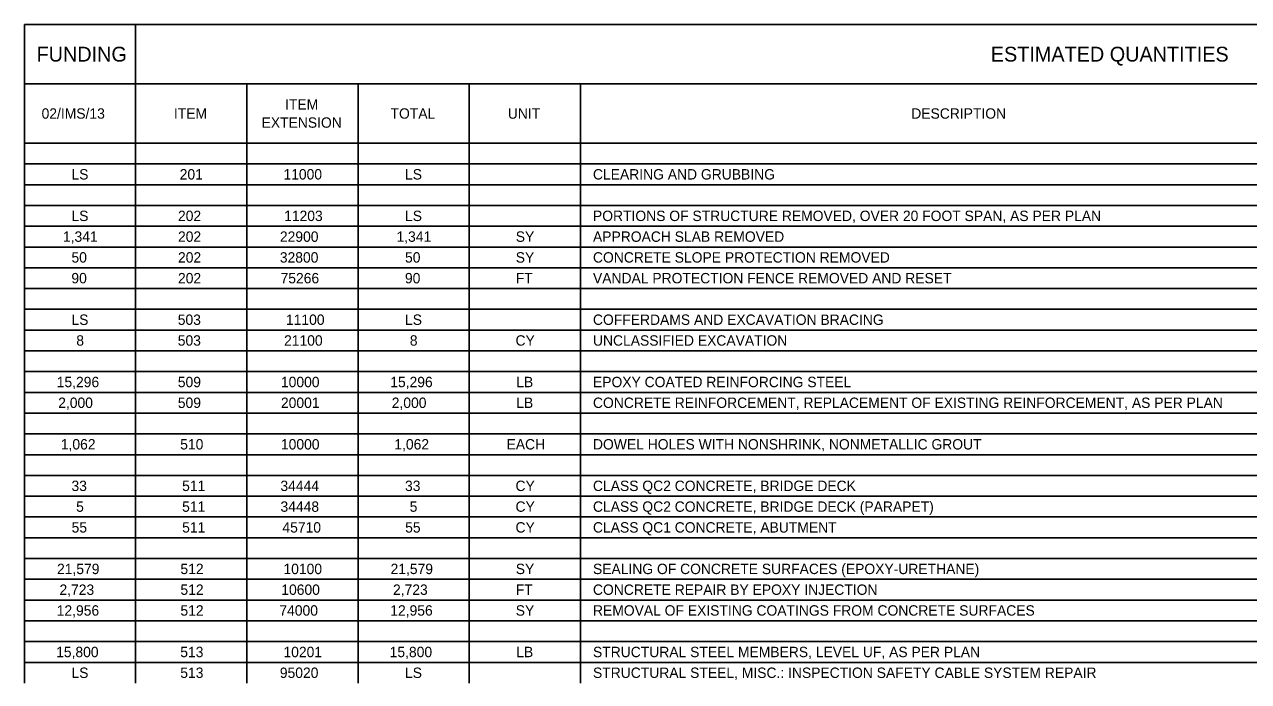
# Model space of a CAD drawing. Extents: x 100 to 128, y 64.8 to 100.
# Drawn here: x 100 to 116.51, y 91.14 to 100 of the extents above; entities that cross this region are included whole.
import ezdxf

# ---------------------------------------------------------------- set-up
doc = ezdxf.new("R2010")
doc.units = 0
doc.layers.add('SH_Text', color=7, linetype='Continuous')

msp = doc.modelspace()

# ---------------------------------------------------------------- linework, layer by layer
at = {"layer": 'SH_Text'}
for p, q in [((100, 100), (128, 100)), ((100, 100), (100, 98.4)), ((101.5, 100), (101.5, 98.4)), ((100, 99.2), (128, 99.2)), ((103, 99.2), (103, 98.4)), ((104.5, 99.2), (104.5, 98.4)), ((106, 99.2), (106, 98.4)), ((107.5, 99.2), (107.5, 98.4)), ((100, 98.4), (128, 98.4)), ((100, 98.4), (128, 98.4)), ((100, 98.4), (100, 95.32)), ((101.5, 98.4), (101.5, 95.32)), ((103, 98.4), (103, 95.32)), ((104.5, 98.4), (104.5, 95.32)), ((106, 98.4), (106, 95.32)), ((107.5, 98.4), (107.5, 95.32)), ((100, 98.12), (128, 98.12)), ((100, 97.84), (128, 97.84)), ((100, 97.56), (128, 97.56)), ((100, 97.28), (128, 97.28)), ((100, 97), (128, 97)), ((100, 96.72), (128, 96.72)), ((100, 96.44), (128, 96.44)), ((100, 96.16), (128, 96.16)), ((100, 95.88), (128, 95.88)), ((100, 95.6), (128, 95.6)), ((100, 95.32), (128, 95.32)), ((100, 95.32), (100, 92.24)), ((101.5, 95.32), (101.5, 92.24)), ((103, 95.32), (103, 92.24)), ((104.5, 95.32), (104.5, 92.24)), ((106, 95.32), (106, 92.24)), ((107.5, 95.32), (107.5, 92.24)), ((100, 95.04), (128, 95.04)), ((100, 94.76), (128, 94.76)), ((100, 94.48), (128, 94.48)), ((100, 94.2), (128, 94.2)), ((100, 93.92), (128, 93.92)), ((100, 93.64), (128, 93.64)), ((100, 93.36), (128, 93.36)), ((100, 93.08), (128, 93.08)), ((100, 92.8), (128, 92.8)), ((100, 92.52), (128, 92.52)), ((100, 92.24), (128, 92.24)), ((100, 92.24), (100, 91.96)), ((101.5, 92.24), (101.5, 91.96)), ((103, 92.24), (103, 91.96)), ((104.5, 92.24), (104.5, 91.96)), ((106, 92.24), (106, 91.96)), ((107.5, 92.24), (107.5, 91.96)), ((100, 91.96), (128, 91.96)), ((100, 91.96), (100, 91.68)), ((101.5, 91.96), (101.5, 91.68)), ((103, 91.96), (103, 91.68)), ((104.5, 91.96), (104.5, 91.68)), ((106, 91.96), (106, 91.68)), ((107.5, 91.96), (107.5, 91.68)), ((100, 91.68), (128, 91.68)), ((100, 91.68), (100, 91.4)), ((101.5, 91.68), (101.5, 91.4)), ((103, 91.68), (103, 91.4)), ((104.5, 91.68), (104.5, 91.4)), ((106, 91.68), (106, 91.4)), ((107.5, 91.68), (107.5, 91.4)), ((100, 91.4), (128, 91.4)), ((100, 91.4), (100, 91.12)), ((101.5, 91.4), (101.5, 91.12)), ((103, 91.4), (103, 91.12)), ((104.5, 91.4), (104.5, 91.12)), ((106, 91.4), (106, 91.12)), ((107.5, 91.4), (107.5, 91.12))]:
    msp.add_line(p, q, dxfattribs=at)

# ---------------------------------------------------------------- texts
for s, height, p in [('FUNDING', 0.2, (100.163, 99.5)), ('ESTIMATED QUANTITIES', 0.2, (113.037, 99.5)), ('ITEM', 0.14, (103.516, 98.852)), ('02/IMS/13', 0.14, (100.231, 98.73)), ('ITEM', 0.14, (102.016, 98.73)), ('TOTAL', 0.14, (104.939, 98.73)), ('UNIT', 0.14, (106.521, 98.73)), ('DESCRIPTION', 0.14, (111.964, 98.73)), ('EXTENSION', 0.14, (103.199, 98.608)), ('LS', 0.14, (100.634, 97.91)), ('201', 0.14, (102.094, 97.91)), ('11000', 0.14, (103.494, 97.91)), ('LS', 0.14, (105.134, 97.91)), ('CLEARING AND GRUBBING', 0.14, (107.67, 97.91)), ('LS', 0.14, (100.634, 97.35)), ('202', 0.14, (102.071, 97.35)), ('11203', 0.14, (103.503, 97.35)), ('LS', 0.14, (105.134, 97.35)), ('PORTIONS OF STRUCTURE REMOVED, OVER 20 FOOT SPAN, AS PER PLAN', 0.14, (107.67, 97.35)), ('1,341', 0.14, (100.519, 97.07)), ('202', 0.14, (102.071, 97.07)), ('22900', 0.14, (103.446, 97.07)), ('1,341', 0.14, (105.019, 97.07)), ('SY', 0.14, (106.628, 97.07)), ('APPROACH SLAB REMOVED', 0.14, (107.67, 97.07)), ('50', 0.14, (100.634, 96.79)), ('202', 0.14, (102.071, 96.79)), ('32800', 0.14, (103.445, 96.79)), ('50', 0.14, (105.134, 96.79)), ('SY', 0.14, (106.628, 96.79)), ('CONCRETE SLOPE PROTECTION REMOVED', 0.14, (107.67, 96.79)), ('90', 0.14, (100.633, 96.51)), ('202', 0.14, (102.071, 96.51)), ('75266', 0.14, (103.455, 96.51)), ('90', 0.14, (105.133, 96.51)), ('FT', 0.14, (106.628, 96.51)), ('VANDAL PROTECTION FENCE REMOVED AND RESET', 0.14, (107.67, 96.51)), ('LS', 0.14, (100.634, 95.95)), ('503', 0.14, (102.068, 95.95)), ('11100', 0.14, (103.528, 95.95)), ('LS', 0.14, (105.134, 95.95)), ('COFFERDAMS AND EXCAVATION BRACING', 0.14, (107.67, 95.95)), ('8', 0.14, (100.699, 95.67)), ('503', 0.14, (102.068, 95.67)), ('21100', 0.14, (103.502, 95.67)), ('8', 0.14, (105.199, 95.67)), ('CY', 0.14, (106.625, 95.67)), ('UNCLASSIFIED EXCAVATION', 0.14, (107.67, 95.67)), ('15,296', 0.14, (100.435, 95.11)), ('509', 0.14, (102.069, 95.11)), ('10000', 0.14, (103.46, 95.11)), ('15,296', 0.14, (104.935, 95.11)), ('LB', 0.14, (106.635, 95.11)), ('EPOXY COATED REINFORCING STEEL', 0.14, (107.67, 95.11)), ('2,000', 0.14, (100.455, 94.83)), ('509', 0.14, (102.069, 94.83)), ('20001', 0.14, (103.46, 94.83)), ('2,000', 0.14, (104.955, 94.83)), ('LB', 0.14, (106.635, 94.83)), ('CONCRETE REINFORCEMENT, REPLACEMENT OF EXISTING REINFORCEMENT, AS PER PLAN', 0.14, (107.67, 94.83)), ('1,062', 0.14, (100.49, 94.27)), ('510', 0.14, (102.101, 94.27)), ('10000', 0.14, (103.46, 94.27)), ('1,062', 0.14, (104.99, 94.27)), ('EACH', 0.14, (106.504, 94.27)), ('DOWEL HOLES WITH NONSHRINK, NONMETALLIC GROUT', 0.14, (107.67, 94.27)), ('33', 0.14, (100.634, 93.71)), ('511', 0.14, (102.127, 93.71)), ('34444', 0.14, (103.453, 93.71)), ('33', 0.14, (105.134, 93.71)), ('CY', 0.14, (106.625, 93.71)), ('CLASS QC2 CONCRETE, BRIDGE DECK', 0.14, (107.67, 93.71)), ('5', 0.14, (100.697, 93.43)), ('511', 0.14, (102.127, 93.43)), ('34448', 0.14, (103.454, 93.43)), ('5', 0.14, (105.197, 93.43)), ('CY', 0.14, (106.625, 93.43)), ('CLASS QC2 CONCRETE, BRIDGE DECK (PARAPET)', 0.14, (107.67, 93.43)), ('55', 0.14, (100.636, 93.15)), ('511', 0.14, (102.127, 93.15)), ('45710', 0.14, (103.48, 93.15)), ('55', 0.14, (105.136, 93.15)), ('CY', 0.14, (106.625, 93.15)), ('CLASS QC1 CONCRETE, ABUTMENT', 0.14, (107.67, 93.15)), ('21,579', 0.14, (100.439, 92.59)), ('512', 0.14, (102.104, 92.59)), ('10100', 0.14, (103.494, 92.59)), ('21,579', 0.14, (104.939, 92.59)), ('SY', 0.14, (106.628, 92.59)), ('SEALING OF CONCRETE SURFACES (EPOXY-URETHANE)', 0.14, (107.67, 92.59)), ('2,723', 0.14, (100.472, 92.31)), ('512', 0.14, (102.104, 92.31)), ('10600', 0.14, (103.465, 92.31)), ('2,723', 0.14, (104.972, 92.31)), ('FT', 0.14, (106.628, 92.31)), ('CONCRETE REPAIR BY EPOXY INJECTION', 0.14, (107.67, 92.31)), ('12,956', 0.14, (100.435, 92.03)), ('512', 0.14, (102.104, 92.03)), ('74000', 0.14, (103.439, 92.03)), ('12,956', 0.14, (104.935, 92.03)), ('SY', 0.14, (106.628, 92.03)), ('REMOVAL OF EXISTING COATINGS FROM CONCRETE SURFACES', 0.14, (107.67, 92.03)), ('15,800', 0.14, (100.427, 91.47)), ('513', 0.14, (102.102, 91.47)), ('10201', 0.14, (103.494, 91.47)), ('15,800', 0.14, (104.927, 91.47)), ('LB', 0.14, (106.635, 91.47)), ('STRUCTURAL STEEL MEMBERS, LEVEL UF, AS PER PLAN', 0.14, (107.67, 91.47)), ('LS', 0.14, (100.634, 91.19)), ('513', 0.14, (102.102, 91.19)), ('95020', 0.14, (103.445, 91.19)), ('LS', 0.14, (105.134, 91.19)), ('STRUCTURAL STEEL, MISC.: INSPECTION SAFETY CABLE SYSTEM REPAIR', 0.14, (107.67, 91.19))]:
    msp.add_text(s, height=height, dxfattribs=at).set_placement(p)

doc.saveas('drawing.dxf')
